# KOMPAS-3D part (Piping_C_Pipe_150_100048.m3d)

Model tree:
1. Plane XY
2. Plane ZX
3. Plane ZY
4. X Axis
5. Y Axis
6. Z Axis
7. Origin
8. Path  (labels: Отвод 90 Dy 150; Труба Dy 150; Фланец Dy 150)
9. Plane of section
10. Section of pipe
11. Pipe
     Толщина стенки 1 = 1

Referenced files in C:\Program Files\ASCON\KOMPAS-3D V10\Libs\Piping\Models\Tanks\: Tanks.a3d
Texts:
  Pipe Dn 150
  Steel ASTM A295
  Three Point Plane
  Plane at Angle
  Line and Point Plane
  Axis through Two Vertices
  Axis of Feature
  Axis of Conical Surface
  Axis through Edge
  Приклеить элемент выдавливания
  Приклеить элемент вращения
  Приклеить кинематический элемент
  Приклеить элемент по сечениям
  Trim by Surface
  Trim by Sketch
  Feature with No History
  Intersection Axis of Two Planes
  Two Line Plane
  Line and Face Plane
  Bend by line
  Hole in sheet body
  Cut in sheet body
  Point in CM
  Linear Dimension from Line to Point
  Surface Finish Symbol
  Geometric Tolerance Symbol
  Текст на чертеже
  Линия-выноска #1
  Линия-выноска #2
  Линия-выноска #3
  Отклонения формы и база
  Марка координационной оси
  Марка/позиционное обозначение с линией-выноской
  Марка/позиционное обозначение на линии
  Марка/позиционное обозначение без линии-выноски
  Отвод 90 Dy 150
  Труба Dy 150
  Фланец Dy 150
